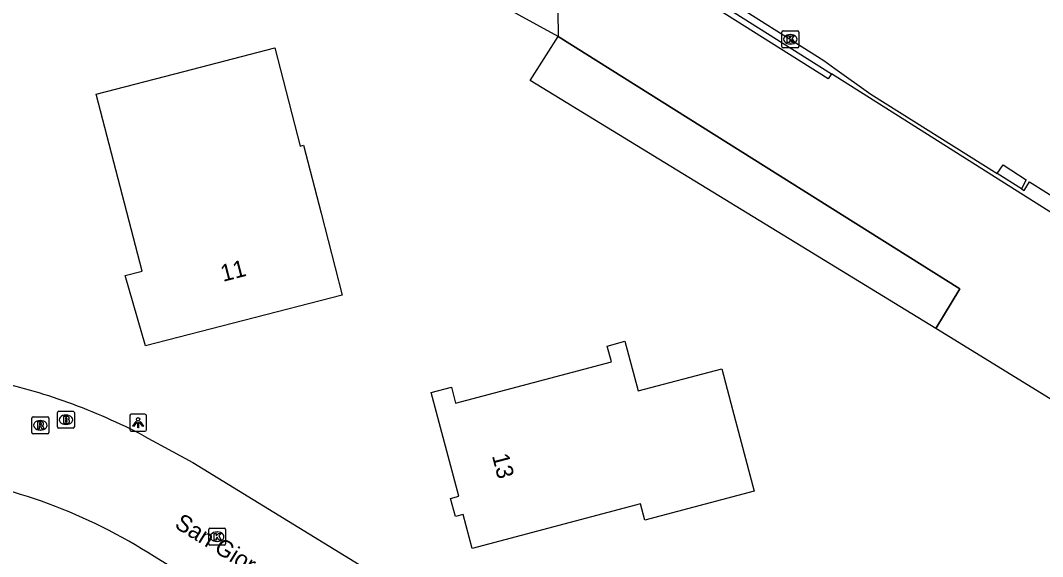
# Model space of a CAD drawing. Extents: x 162157 to 163165, y 378998 to 380775.
# Drawn here: x 162568.2 to 162628.7, y 380679.9 to 380711.7 of the extents above; entities that cross this region are included whole.
import ezdxf

# ---------------------------------------------------------------- set-up
doc = ezdxf.new("R2010")
doc.units = 0
for name, color, linetype in [('IMGEO_Brandkraan', 7, 'Continuous'), ('IMGEO_Gemengd_bos', 7, 'Continuous'), ('IMGEO_Grasland_overig', 7, 'Continuous'), ('IMGEO_Hek', 7, 'Continuous'), ('IMGEO_Kolk', 7, 'Continuous'), ('IMGEO_Lichtpunt', 7, 'Continuous'), ('IMGEO_Openbare_ruimte_label', 7, 'Continuous'), ('IMGEO_Pand', 7, 'Continuous'), ('IMGEO_Pand_nummerreeks', 7, 'Continuous'), ('IMGEO_Rijbaan_lokaal_open', 7, 'Continuous'), ('IMGEO_Rioolput', 7, 'Continuous'), ('IMGEO_Voetpad_open', 7, 'Continuous')]:
    doc.layers.add(name, color=color, linetype=linetype)

msp = doc.modelspace()

# ---------------------------------------------------------------- linework, layer by layer
at = {"layer": 'IMGEO_Brandkraan'}
for p, q in [((162570.413, 380687.59), (162570.413, 380688.442)), ((162570.488, 380688.516), (162571.34, 380688.516)), ((162570.901, 380688.296), (162570.926, 380688.296)), ((162571.414, 380688.442), (162571.414, 380687.59)), ((162570.924, 380687.736), (162570.899, 380687.736)), ((162571.34, 380687.516), (162570.488, 380687.516))]:
    msp.add_line(p, q, dxfattribs=at)
for points in [[(162570.413, 380687.59), (162570.413, 380688.442)], [(162570.488, 380688.516), (162571.34, 380688.516)], [(162571.414, 380688.442), (162571.414, 380687.59)], [(162570.761, 380688.216), (162570.761, 380687.816), (162570.974, 380687.816)], [(162570.992, 380688.216), (162570.761, 380688.216)], [(162570.94, 380688.135), (162570.886, 380688.135), (162570.886, 380688.059)], [(162570.886, 380688.059), (162570.939, 380688.059)], [(162570.948, 380687.983), (162570.886, 380687.983), (162570.886, 380687.902)], [(162570.886, 380687.902), (162570.948, 380687.902)], [(162571.34, 380687.516), (162570.488, 380687.516)]]:
    msp.add_lwpolyline(points, dxfattribs=at)
for centre, radius, start, end in [((162570.49, 380688.44), 0.0765, 91.55205, 178.44795), ((162570.49, 380688.44), 0.0765, 91.55205, 178.44795), ((162571.338, 380688.44), 0.0765, 1.55205, 88.44795), ((162571.338, 380688.44), 0.0765, 1.55205, 88.44795), ((162570.941, 380688.097), 0.0379, 267.82845, 90.93552), ((162570.949, 380687.942), 0.0404, 269.87594, 90.50774), ((162570.98, 380688.067), 0.251, 268.66757, 293.53466), ((162570.996, 380688.071), 0.145, 59.4692, 91.53667), ((162571.021, 380688.118), 0.0922, 285.51372, 58.15012), ((162571.026, 380687.926), 0.105, 301.31148, 78.98903), ((162570.49, 380687.592), 0.0765, 181.55205, 268.44795), ((162570.49, 380687.592), 0.0765, 181.55205, 268.44795), ((162571.338, 380687.592), 0.0765, 271.55205, 358.44795), ((162571.338, 380687.592), 0.0765, 271.55205, 358.44795)]:
    msp.add_arc(centre, radius, start, end, dxfattribs=at)
for centre, major_axis, ratio, start_param, end_param in [((162570.9, 380688.016), (-0.387, 0.002), 0.722429, 4.712389, 7.853982), ((162570.925, 380688.016), (-0.39, 0.002), 0.717154, 1.570796, 4.712389)]:
    msp.add_ellipse(centre, major_axis=major_axis, ratio=ratio, start_param=start_param, end_param=end_param, dxfattribs=at)
at = {"layer": 'IMGEO_Gemengd_bos'}
for points in [[(162600.057, 380710.71), (162580.923, 380721.172), (162569.829, 380726.567), (162546.168, 380720.369)], [(162599.944, 380718.331), (162600.057, 380710.71)], [(162600.057, 380710.71), (162623.828, 380695.769), (162622.41, 380693.42)], [(162631.511, 380698.842), (162628.196, 380700.938), (162616.228, 380708.496)], [(162651.018, 380675.815), (162622.41, 380693.42)]]:
    msp.add_lwpolyline(points, dxfattribs=at)
at = {"layer": 'IMGEO_Grasland_overig'}
msp.add_lwpolyline([(162622.41, 380693.42), (162598.391, 380708.095), (162600.057, 380710.71)], dxfattribs=at)
at = {"layer": 'IMGEO_Hek'}
msp.add_lwpolyline([(162622.41, 380693.42), (162623.828, 380695.769), (162600.057, 380710.71)], dxfattribs=at)
at = {"layer": 'IMGEO_Kolk'}
for p, q in [((162613.293, 380710.112), (162613.293, 380710.964)), ((162613.368, 380711.038), (162614.22, 380711.038)), ((162613.781, 380710.818), (162613.806, 380710.818)), ((162614.294, 380710.964), (162614.294, 380710.112)), ((162613.804, 380710.258), (162613.779, 380710.258)), ((162614.22, 380710.038), (162613.368, 380710.038)), ((162579.365, 380680.666), (162579.365, 380681.518)), ((162579.44, 380681.592), (162580.292, 380681.592)), ((162579.853, 380681.372), (162579.878, 380681.372)), ((162580.366, 380681.518), (162580.366, 380680.666)), ((162580.292, 380680.592), (162579.44, 380680.592)), ((162579.876, 380680.812), (162579.851, 380680.812))]:
    msp.add_line(p, q, dxfattribs=at)
for points in [[(162613.293, 380710.112), (162613.293, 380710.964)], [(162613.368, 380711.038), (162614.22, 380711.038)], [(162613.614, 380710.738), (162613.737, 380710.738), (162613.737, 380710.587), (162613.867, 380710.738), (162614.031, 380710.738), (162613.885, 380710.587), (162614.038, 380710.338), (162613.886, 380710.338), (162613.801, 380710.502), (162613.737, 380710.435), (162613.737, 380710.338), (162613.614, 380710.338), (162613.614, 380710.738)], [(162614.294, 380710.964), (162614.294, 380710.112)], [(162614.22, 380710.038), (162613.368, 380710.038)], [(162579.365, 380680.666), (162579.365, 380681.518)], [(162579.44, 380681.592), (162580.292, 380681.592)], [(162579.686, 380681.292), (162579.809, 380681.292), (162579.809, 380681.141), (162579.939, 380681.292), (162580.103, 380681.292), (162579.957, 380681.141), (162580.11, 380680.892), (162579.958, 380680.892), (162579.873, 380681.056), (162579.809, 380680.989), (162579.809, 380680.892), (162579.686, 380680.892), (162579.686, 380681.292)], [(162580.366, 380681.518), (162580.366, 380680.666)], [(162580.292, 380680.592), (162579.44, 380680.592)]]:
    msp.add_lwpolyline(points, dxfattribs=at)
for centre, start, end in [((162613.37, 380710.962), 91.55205, 178.44795), ((162613.37, 380710.962), 91.55205, 178.44795), ((162614.218, 380710.962), 1.55205, 88.44795), ((162614.218, 380710.962), 1.55205, 88.44795), ((162613.37, 380710.114), 181.55205, 268.44795), ((162613.37, 380710.114), 181.55205, 268.44795), ((162614.218, 380710.114), 271.55205, 358.44795), ((162614.218, 380710.114), 271.55205, 358.44795), ((162579.442, 380681.516), 91.55205, 178.44795), ((162579.442, 380681.516), 91.55205, 178.44795), ((162580.29, 380681.516), 1.55205, 88.44795), ((162580.29, 380681.516), 1.55205, 88.44795), ((162579.442, 380680.668), 181.55205, 268.44795), ((162579.442, 380680.668), 181.55205, 268.44795), ((162580.29, 380680.668), 271.55205, 358.44795), ((162580.29, 380680.668), 271.55205, 358.44795)]:
    msp.add_arc(centre, 0.0765, start, end, dxfattribs=at)
for centre, major_axis, ratio, start_param, end_param in [((162613.78, 380710.538), (-0.387, 0.002), 0.722429, 4.712389, 7.853982), ((162613.805, 380710.538), (-0.39, 0.002), 0.717154, 1.570796, 4.712389), ((162579.852, 380681.092), (-0.387, 0.002), 0.722429, 4.712389, 7.853982), ((162579.877, 380681.092), (-0.39, 0.002), 0.717154, 1.570796, 4.712389)]:
    msp.add_ellipse(centre, major_axis=major_axis, ratio=ratio, start_param=start_param, end_param=end_param, dxfattribs=at)
at = {"layer": 'IMGEO_Lichtpunt'}
for p, q in [((162575.591, 380688.338), (162574.783, 380688.338)), ((162575.591, 380688.338), (162574.783, 380688.338)), ((162574.689, 380688.243), (162574.689, 380687.436)), ((162574.689, 380688.243), (162574.689, 380687.436)), ((162575.685, 380687.436), (162575.685, 380688.243)), ((162575.685, 380687.436), (162575.685, 380688.243)), ((162574.783, 380687.342), (162575.591, 380687.342)), ((162574.783, 380687.342), (162575.591, 380687.342))]:
    msp.add_line(p, q, dxfattribs=at)
for points in [[(162575.063, 380687.907), (162575.102, 380687.879), (162574.914, 380687.617), (162574.876, 380687.644), (162575.063, 380687.907)], [(162575.165, 380687.859), (162575.212, 380687.859), (162575.212, 380687.537), (162575.165, 380687.537), (162575.165, 380687.859)], [(162575.275, 380687.879), (162575.313, 380687.906), (162575.5, 380687.644), (162575.461, 380687.616), (162575.275, 380687.879)]]:
    msp.add_lwpolyline(points, dxfattribs=at)
msp.add_circle((162575.188, 380688.041), 0.0994, dxfattribs=at)
for centre, start, end in [((162574.783, 380688.243), 90, 180), ((162574.783, 380688.243), 90, 180), ((162575.591, 380688.243), 0, 90), ((162575.591, 380688.243), 0, 90), ((162574.783, 380687.436), 180, 270), ((162574.783, 380687.436), 180, 270), ((162575.591, 380687.436), 270, 0), ((162575.591, 380687.436), 270, 360)]:
    msp.add_arc(centre, 0.0946, start, end, dxfattribs=at)
at = {"layer": 'IMGEO_Pand'}
for points in [[(162587.274, 380695.398), (162575.615, 380692.382), (162574.423, 380696.555), (162575.425, 380696.814), (162572.713, 380707.298), (162577.89, 380708.637), (162583.279, 380710.031), (162584.785, 380704.211), (162584.981, 380704.262), (162586.022, 380700.239), (162587.274, 380695.398)], [(162594.959, 380680.393), (162594.423, 380682.415), (162593.969, 380682.295), (162593.688, 380683.356), (162594.17, 380683.484), (162592.543, 380689.625), (162593.732, 380689.94), (162593.982, 380688.996), (162603.204, 380691.44), (162602.955, 380692.379), (162604.007, 380692.658), (162604.785, 380689.723), (162609.739, 380691.037), (162610.38, 380688.618), (162611.662, 380683.784), (162605.182, 380682.066), (162604.925, 380683.035), (162594.959, 380680.393)]]:
    msp.add_lwpolyline(points, dxfattribs=at)
at = {"layer": 'IMGEO_Rijbaan_lokaal_open'}
for points in [[(162599.351, 380719.667), (162603.604, 380716.929), (162608.539, 380713.863), (162609.529, 380713.248), (162615.77, 380709.281), (162616.426, 380708.812), (162618.561, 380707.284), (162626.041, 380702.586)], [(162626.041, 380702.586), (162626.396, 380703.105), (162627.751, 380702.216), (162627.474, 380701.687)], [(162627.474, 380701.687), (162627.636, 380701.585), (162627.962, 380702.1), (162631.97, 380699.575), (162633.747, 380698.455), (162634.335, 380698.085)], [(162575.536, 380687.053), (162578.417, 380685.49), (162602.91, 380670.466), (162622.562, 380658.412)], [(162619.667, 380653.081), (162606.957, 380660.916), (162594.316, 380668.708), (162576.131, 380679.918)]]:
    msp.add_lwpolyline(points, dxfattribs=at)
for centre, radius, start, end in [((162558.721, 380654.788), 36.392, 70.23625, 77.76425), ((162558.975, 380655.53), 35.609, 62.28373, 70.21643), ((162558.881, 380653.204), 31.8, 57.14824, 82.38453)]:
    msp.add_arc(centre, radius, start, end, dxfattribs=at)
at = {"layer": 'IMGEO_Rioolput'}
for p, q in [((162568.896, 380687.261), (162568.896, 380688.113)), ((162568.971, 380688.187), (162569.823, 380688.187)), ((162569.384, 380687.967), (162569.409, 380687.967)), ((162569.897, 380688.113), (162569.897, 380687.261)), ((162569.823, 380687.187), (162568.971, 380687.187)), ((162569.407, 380687.407), (162569.382, 380687.407))]:
    msp.add_line(p, q, dxfattribs=at)
for points in [[(162568.896, 380687.261), (162568.896, 380688.113)], [(162568.971, 380688.187), (162569.823, 380688.187)], [(162569.485, 380687.885), (162569.233, 380687.887), (162569.233, 380687.487)], [(162569.411, 380687.806), (162569.357, 380687.806), (162569.357, 380687.725)], [(162569.357, 380687.725), (162569.409, 380687.725)], [(162569.897, 380688.113), (162569.897, 380687.261)], [(162569.823, 380687.187), (162568.971, 380687.187)], [(162569.233, 380687.487), (162569.357, 380687.487), (162569.357, 380687.649), (162569.368, 380687.649)], [(162569.415, 380687.62), (162569.486, 380687.487), (162569.626, 380687.487), (162569.561, 380687.613)]]:
    msp.add_lwpolyline(points, dxfattribs=at)
for centre, radius, start, end in [((162568.973, 380688.111), 0.0765, 91.55205, 178.44795), ((162568.973, 380688.111), 0.0765, 91.55205, 178.44795), ((162569.393, 380687.914), 0.19, 274.7715, 282.96867), ((162569.417, 380687.71), 0.0964, 77.00612, 93.18647), ((162569.431, 380687.767), 0.0378, 276.66336, 79.67722), ((162569.484, 380687.775), 0.109, 350.36119, 89.41601), ((162569.482, 380687.775), 0.112, 277.58423, 350.98172), ((162569.821, 380688.111), 0.0765, 1.55205, 88.44795), ((162569.821, 380688.111), 0.0765, 1.55205, 88.44795), ((162568.973, 380687.263), 0.0765, 181.55205, 268.44795), ((162568.973, 380687.263), 0.0765, 181.55205, 268.44795), ((162569.367, 380687.596), 0.0533, 26.02933, 88.69889), ((162569.466, 380687.56), 0.108, 29.51342, 73.79051), ((162569.821, 380687.263), 0.0765, 271.55205, 358.44795), ((162569.821, 380687.263), 0.0765, 271.55205, 358.44795)]:
    msp.add_arc(centre, radius, start, end, dxfattribs=at)
for centre, major_axis, ratio, start_param, end_param in [((162569.383, 380687.687), (-0.387, 0.002), 0.722429, 4.712389, 7.853982), ((162569.408, 380687.687), (-0.39, 0.002), 0.717154, 1.570796, 4.712389)]:
    msp.add_ellipse(centre, major_axis=major_axis, ratio=ratio, start_param=start_param, end_param=end_param, dxfattribs=at)
at = {"layer": 'IMGEO_Voetpad_open'}
for points in [[(162616.228, 380708.496), (162616.035, 380708.189), (162599.944, 380718.331)], [(162600.7, 380718.224), (162601.737, 380717.567), (162602.901, 380716.913), (162616.228, 380708.496)], [(162627.474, 380701.687), (162626.041, 380702.586)]]:
    msp.add_lwpolyline(points, dxfattribs=at)

# ---------------------------------------------------------------- texts
at = {"layer": 'IMGEO_Openbare_ruimte_label'}
msp.add_text('San Giorgilaan', height=1, rotation=328.45633, dxfattribs=at).set_placement((162577.284, 380681.671))
at = {"layer": 'IMGEO_Pand_nummerreeks'}
for s, rotation, p in [('11', 14.50156, (162580.211, 380696.175)), ('13', 284.64552, (162596.128, 380685.885))]:
    msp.add_text(s, height=1, rotation=rotation, dxfattribs=at).set_placement(p)

doc.saveas('drawing.dxf')
